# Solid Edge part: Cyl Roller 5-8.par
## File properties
Title: Cyl Roller 5-8
Author: Dan
Comments: Seun 421 5122 Ideal Precision Grinders  Grant 425 3631
Template: Normal.par
Last saved by: Dan
Revision: 10
Application: Solid Edge
Density: 0 kg/mm^3
Accuracy: 0.99
Document Number: P52-004-5
Project Name: Piston Pump P52
Material: steel
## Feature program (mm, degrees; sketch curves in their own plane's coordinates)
sketch for "unnamed Protrusion 1" plane through (0, 0, 0) normal (1, 0, 0) x-axis (0, 1, 0)
  circle centre (0, 0) radius 2.5
extrude "unnamed Protrusion 1" add finite 8 symmetric
fillet "Round_1" radius 0.3
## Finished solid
Body 1: solid body, 5 faces, 4 edges, 0 vertices.
  Faces by surface: plane 2, torus 2, cylinder 1
  Edges by curve: circle 4
Bounding box of the edges (mm; curved faces can reach further): 8.000 x 5.000 x 5.000, from (-4, -2.5, -2.5) to (4, 2.5, 2.5).
Cylindrical faces by radius (mm): R2.5 x1
Toroidal faces (ring radius, tube radius in mm): R2.2 r0.3 x2
Planar faces by outward normal: +x 1, -x 1
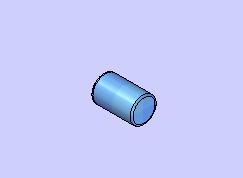
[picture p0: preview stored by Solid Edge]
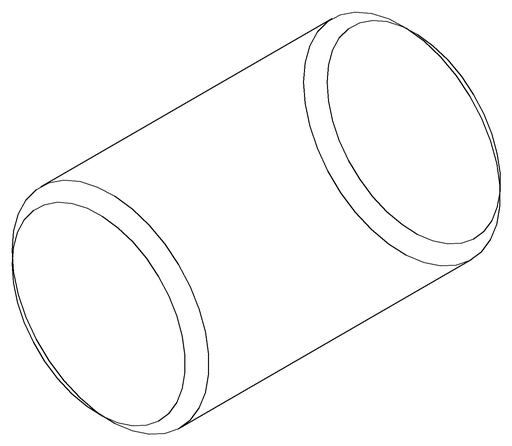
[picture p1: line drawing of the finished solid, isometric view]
